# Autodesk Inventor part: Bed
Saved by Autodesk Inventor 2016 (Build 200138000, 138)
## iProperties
Created: 2016-03
Part Number: Bed
Material: Generic
Document SubType Name: Modeling
Designer: bongo_000
Density: 1 g/cm^3
Appearance: Default
Author: bongo_000
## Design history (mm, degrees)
feature "Base1"
body "Solid1"
